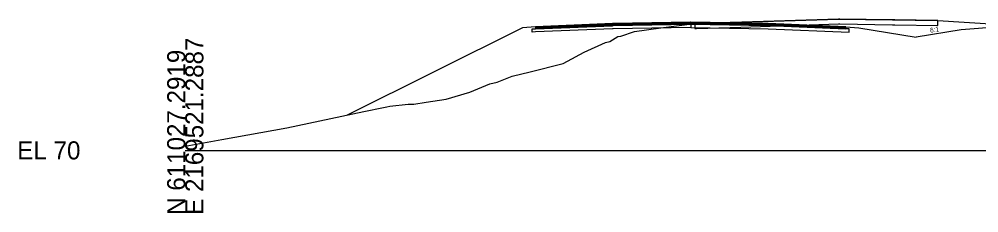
# Model space of a CAD drawing. Extents: x -26 to 1303, y -3010 to 12033.
# Drawn here: x 974.3 to 1122.8, y 6990.3 to 7020.4 of the extents above; entities that cross this region are included whole.
import ezdxf

# ---------------------------------------------------------------- set-up
doc = ezdxf.new("R2010")
doc.units = 0
for name, color, linetype in [('RD_GPK_XS_Cell', 7, 'Continuous'), ('RD_XS_Base', 7, 'Continuous'), ('RD_XS_ExGround', 7, 'Continuous'), ('RD_XS_ExPaveRet', 7, 'Continuous'), ('RD_XS_Greenside', 7, 'Continuous'), ('RD_XS_Pave', 7, 'Continuous'), ('RD_XS_PaveOvlay_CP', 7, 'Continuous'), ('RD_XS_TieSlope', 7, 'Continuous'), ('RD_XS_TX_Slope', 7, 'Continuous')]:
    doc.layers.add(name, color=color, linetype=linetype)

msp = doc.modelspace()

# ---------------------------------------------------------------- linework, layer by layer
at = {"layer": 'RD_GPK_XS_Cell'}
msp.add_line((1000, 7000), (1150, 7000), dxfattribs=at)
at = {"layer": 'RD_XS_Base'}
for p, q in [((1053.68, 7018.84), (1054.17, 7018.86)), ((1053.68, 7018.83), (1053.68, 7018.84)), ((1053.68, 7018.34), (1053.68, 7018.83)), ((1054.17, 7018.86), (1054.18, 7018.86)), ((1054.18, 7018.86), (1066.08, 7019.33)), ((1066.08, 7018.83), (1054.18, 7018.36)), ((1066.08, 7019.33), (1066.18, 7019.34)), ((1066.18, 7018.84), (1066.08, 7018.83)), ((1066.18, 7019.34), (1078.17, 7019.58)), ((1078.17, 7019.08), (1066.18, 7018.84)), ((1078.17, 7019.58), (1078.18, 7019.58)), ((1078.18, 7019.08), (1078.17, 7019.08)), ((1078.18, 7019.58), (1078.18, 7019.74)), ((1078.18, 7019.74), (1078.18, 7019.74)), ((1078.18, 7019.74), (1078.18, 7019.74)), ((1078.18, 7019.74), (1078.18, 7019.08)), ((1078.18, 7019.58), (1078.18, 7019.74)), ((1078.18, 7019.74), (1078.18, 7019.08)), ((1078.18, 7019.58), (1078.18, 7019.58)), ((1078.18, 7019.58), (1078.18, 7019.08)), ((1078.19, 7019.58), (1078.18, 7019.58)), ((1078.18, 7019.58), (1078.18, 7019.08)), ((1090.18, 7019.34), (1078.18, 7019.58)), ((1078.18, 7019.58), (1078.18, 7019.58)), ((1078.18, 7019.08), (1078.19, 7019.08)), ((1078.18, 7019.08), (1078.18, 7019.08)), ((1078.18, 7019.08), (1078.18, 7019.08)), ((1078.18, 7019.08), (1090.18, 7018.84)), ((1102.18, 7018.86), (1090.18, 7019.34)), ((1090.18, 7018.84), (1102.68, 7018.34)), ((1092.18, 7019.26), (1092.18, 7019.26)), ((1092.18, 7018.76), (1092.18, 7018.76)), ((1102.68, 7018.84), (1102.18, 7018.86)), ((1102.18, 7018.86), (1102.18, 7018.86)), ((1102.68, 7018.34), (1102.68, 7018.84)), ((1102.68, 7018.84), (1102.68, 7018.84)), ((1054.17, 7018.36), (1053.68, 7018.34)), ((1054.18, 7018.36), (1054.17, 7018.36)), ((1102.68, 7018.34), (1102.68, 7018.34)), ((1102.68, 7018.34), (1102.68, 7018.34))]:
    msp.add_line(p, q, dxfattribs=at)
at = {"layer": 'RD_XS_ExGround'}
msp.add_lwpolyline([(1000, 7000.65), (1005.67, 7001.67), (1015.69, 7003.47), (1027.61, 7006.01), (1030.65, 7006.66), (1031.2, 7006.75), (1031.63, 7006.85), (1034.48, 7007.15), (1035.34, 7007.15), (1037.24, 7007.45), (1040.35, 7007.94), (1044, 7009.03), (1047.11, 7010.31), (1048.26, 7010.56), (1050.54, 7011.5), (1053.35, 7012.17), (1058.44, 7013.46), (1059.11, 7013.83), (1061.7, 7015.22), (1064.99, 7016.74), (1065.68, 7016.89), (1066.89, 7017.66), (1067.37, 7017.72), (1069.47, 7018.45), (1073.58, 7018.98), (1078.81, 7019.65), (1084.3, 7019.81), (1101.07, 7020.35), (1109.39, 7020.24), (1116.42, 7020.14), (1125.36, 7019.55)], dxfattribs=at)
at = {"layer": 'RD_XS_ExPaveRet'}
msp.add_lwpolyline([(1078.81, 7019.65), (1078.81, 7019.64), (1078.81, 7018.9), (1079.07, 7018.91), (1084.3, 7019.06), (1084.46, 7019.07), (1101.07, 7019.6), (1101.24, 7019.6), (1109.39, 7019.49), (1109.78, 7019.49), (1116.42, 7019.39), (1116.42, 7019.42), (1116.42, 7020.14), (1109.78, 7020.24), (1109.39, 7020.24), (1101.24, 7020.35), (1101.07, 7020.35), (1084.46, 7019.82), (1084.3, 7019.81), (1079.07, 7019.66), (1078.81, 7019.65)], dxfattribs=at)
msp.add_lwpolyline([(1078.81, 7019.65), (1078.81, 7019.64), (1078.81, 7018.9), (1079.07, 7018.91), (1084.3, 7019.06), (1084.46, 7019.07), (1101.07, 7019.6), (1101.24, 7019.6), (1109.39, 7019.49), (1109.78, 7019.49), (1116.42, 7019.39), (1116.42, 7019.42), (1116.42, 7020.14), (1109.78, 7020.24), (1109.39, 7020.24), (1101.24, 7020.35), (1101.07, 7020.35), (1084.46, 7019.82), (1084.3, 7019.81), (1079.07, 7019.66), (1078.81, 7019.65)], dxfattribs=at)
at = {"layer": 'RD_XS_Greenside'}
for p, q in [((1052.18, 7019.02), (1025.05, 7005.45)), ((1104.18, 7019.02), (1113.05, 7017.54)), ((1120, 7018.7), (1113.05, 7017.54))]:
    msp.add_line(p, q, dxfattribs=at)
at = {"layer": 'RD_XS_Pave'}
for p, q in [((1078.17, 7019.9), (1066.18, 7019.66)), ((1078.18, 7019.9), (1078.17, 7019.9)), ((1078.19, 7019.9), (1078.18, 7019.9)), ((1090.18, 7019.66), (1078.18, 7019.9)), ((1066.08, 7019.65), (1054.18, 7019.18)), ((1066.08, 7019.49), (1054.18, 7019.02)), ((1054.18, 7019.02), (1066.08, 7019.49)), ((1054.18, 7018.86), (1066.08, 7019.33)), ((1054.18, 7019.18), (1054.18, 7019.17)), ((1054.18, 7019.17), (1054.18, 7019.02)), ((1054.18, 7019.02), (1054.18, 7019.01)), ((1054.18, 7019.01), (1054.18, 7018.86)), ((1066.18, 7019.66), (1066.08, 7019.65)), ((1066.18, 7019.5), (1066.08, 7019.49)), ((1066.08, 7019.49), (1066.18, 7019.5)), ((1066.08, 7019.33), (1066.18, 7019.34)), ((1078.17, 7019.74), (1066.18, 7019.5)), ((1066.18, 7019.5), (1078.17, 7019.74)), ((1066.18, 7019.34), (1078.17, 7019.58)), ((1078.18, 7019.74), (1078.17, 7019.74)), ((1078.17, 7019.74), (1078.18, 7019.74)), ((1078.17, 7019.58), (1078.18, 7019.58)), ((1078.18, 7019.58), (1078.18, 7019.74)), ((1078.18, 7019.74), (1078.18, 7019.74)), ((1078.18, 7019.74), (1078.19, 7019.74)), ((1078.19, 7019.74), (1078.18, 7019.74)), ((1078.18, 7019.74), (1078.18, 7019.74)), ((1078.18, 7019.74), (1078.18, 7019.58)), ((1078.18, 7019.58), (1078.18, 7019.74)), ((1078.18, 7019.74), (1090.18, 7019.5)), ((1090.18, 7019.5), (1078.18, 7019.74)), ((1078.18, 7019.74), (1078.18, 7019.58)), ((1078.18, 7019.58), (1078.19, 7019.58)), ((1078.18, 7019.58), (1078.18, 7019.58)), ((1078.18, 7019.58), (1078.18, 7019.58)), ((1078.18, 7019.58), (1090.18, 7019.34)), ((1102.18, 7019.18), (1090.18, 7019.66)), ((1090.18, 7019.5), (1102.18, 7019.02)), ((1102.18, 7019.02), (1090.18, 7019.5)), ((1090.18, 7019.34), (1102.18, 7018.86)), ((1092.18, 7019.58), (1092.18, 7019.58)), ((1092.18, 7019.42), (1092.18, 7019.42)), ((1092.18, 7019.42), (1092.18, 7019.42)), ((1092.18, 7019.26), (1092.18, 7019.26)), ((1102.18, 7019.02), (1102.18, 7019.18)), ((1102.18, 7019.18), (1102.18, 7019.18)), ((1102.18, 7019.02), (1102.18, 7019.02)), ((1102.18, 7019.02), (1102.18, 7019.02)), ((1102.18, 7018.86), (1102.18, 7019.02)), ((1102.18, 7019.02), (1102.18, 7019.02)), ((1102.18, 7018.86), (1102.18, 7018.86)), ((1102.18, 7018.86), (1102.18, 7018.86))]:
    msp.add_line(p, q, dxfattribs=at)
at = {"layer": 'RD_XS_PaveOvlay_CP'}
for p, q in [((1066.18, 7019.66), (1078.18, 7019.9)), ((1078.18, 7019.9), (1090.18, 7019.66)), ((1054.18, 7019.18), (1066.18, 7019.66)), ((1090.18, 7019.66), (1102.18, 7019.18))]:
    msp.add_line(p, q, dxfattribs=at)
at = {"layer": 'RD_XS_TieSlope'}
for p, q in [((1054.18, 7019.18), (1052.18, 7019.02)), ((1102.18, 7019.18), (1104.18, 7019.02)), ((1126, 7019.18), (1120, 7018.7))]:
    msp.add_line(p, q, dxfattribs=at)

# ---------------------------------------------------------------- texts
at = {"layer": 'RD_GPK_XS_Cell'}
for s, p in [('E 2169521.2887', (1002.8, 6990)), ('N 611027.2919', (1000, 6990))]:
    msp.add_text(s, height=2.8, rotation=90, dxfattribs=at).set_placement(p)
msp.add_text('EL 70', height=2.8, dxfattribs=at).set_placement((974, 6998.6))
at = {"layer": 'RD_XS_TX_Slope'}
msp.add_text('6:1', height=0.75, rotation=9.4642, dxfattribs=at).set_placement((1115.25, 7018.23))

doc.saveas('drawing.dxf')
